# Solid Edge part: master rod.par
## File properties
Author: Administrator
Template: normal.par
Last saved by: Cadcim
Revision: 11
Application: Solid Edge
Accuracy: 0.99
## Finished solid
Body 1: solid body, 60 faces, 148 edges, 80 vertices.
  Faces by surface: cylinder 42, plane 18
  Edges by curve: circle 78, line 58, ellipse 12
Bounding box of the edges (mm): 320.500 x 112.000 x 70.000, from (-118.4884, -56, -35) to (202.0116, 56, 35).
Cylindrical faces by radius (mm): R5 x8, R6 x4, R12 x1, R13 x8, R17.5 x1, R26 x1, R31.5 x3, R35 x2, R72.03 x8, R78 x4, R207.0766 x1, R207.2725 x1
Planar faces by outward normal: +y 2, +z 5, -y 2, -z 5, oblique 4
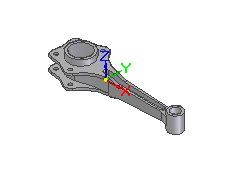
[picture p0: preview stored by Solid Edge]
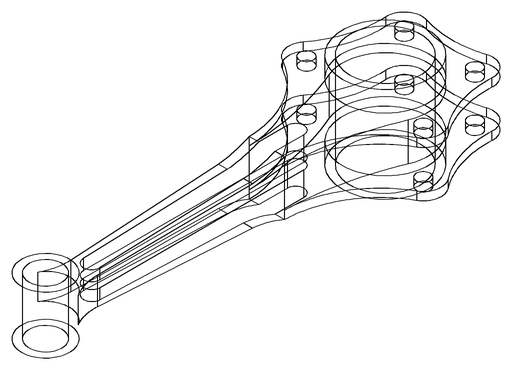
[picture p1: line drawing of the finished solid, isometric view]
